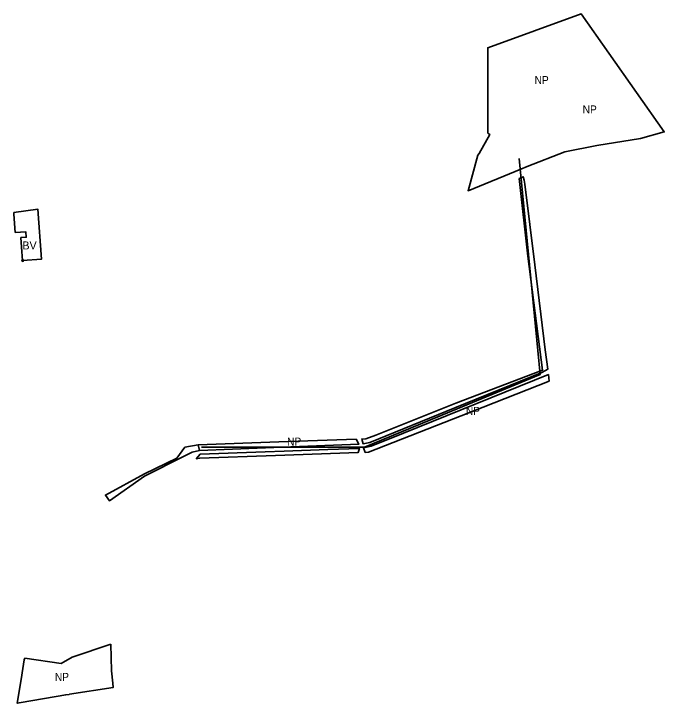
# Model space of a CAD drawing. Extents: x -650276 to -642489, y -1074311 to -1066658.
# Drawn here: x -643464 to -642489, y -1070593 to -1069560 of the extents above; entities that cross this region are included whole.
import ezdxf

# ---------------------------------------------------------------- set-up
doc = ezdxf.new("R2010")
doc.units = 0
doc.header["$LTSCALE"] = 4.8
doc.header["$PDMODE"] = 32
doc.header["$PDSIZE"] = 2.4
for name, color, linetype, lineweight in [('3', 7, 'Continuous', 35), ('48', 7, 'Continuous', 35), ('54', 7, 'Continuous', 35)]:
    doc.layers.add(name, color=color, linetype=linetype, lineweight=lineweight)
doc.layers.add('62', color=7, linetype='Continuous')

msp = doc.modelspace()

# ---------------------------------------------------------------- linework, layer by layer
at = {"layer": '3'}
for points in [[(-643450.3, -1069929.7), (-643422.204, -1069927.68), (-643427.6, -1069852.59), (-643463.51, -1069857.44)], [(-643463.51, -1069857.44), (-643463.31, -1069860.18), (-643461.327, -1069887.84)], [(-643461.327, -1069887.84), (-643445.37, -1069886.7), (-643444.79, -1069894.68), (-643452.77, -1069895.25), (-643451.74, -1069909.63), (-643450.3, -1069929.7)]]:
    msp.add_lwpolyline(points, dxfattribs=at)
msp.add_point((-643450.3, -1069929.7), dxfattribs=at)
at = {"layer": '48'}
for points in [[(-642589.86, -1069757.1), (-642524.14, -1069746.8), (-642488.71, -1069736.85), (-642613.34, -1069559.68), (-642753.18, -1069610.65), (-642753.25, -1069738.59), (-642750.08, -1069740.57), (-642766.27, -1069769), (-642767.89, -1069771.42), (-642782.69, -1069824.93), (-642703.57, -1069792.88), (-642693.99, -1069788.85), (-642637.44, -1069766.81)], [(-642706.3, -1069806.69), (-642693.2, -1069922.89), (-642671.23, -1070094.16), (-642801.19, -1070143.75), (-642921.03, -1070191.32), (-642936.02, -1070197.23), (-642942.12, -1070197.4), (-642940.12, -1070204.42), (-642930.02, -1070202.54), (-642802.38, -1070150.51), (-642671.9, -1070097.32), (-642663.28, -1070092.67), (-642667.19, -1070063.71), (-642682.78, -1069935.98), (-642697.64, -1069815.14), (-642698.77, -1069809.17), (-642700.34, -1069804.12), (-642701.17, -1069804.49)], [(-642936.88, -1070217.27), (-642931.88, -1070217.1), (-642792.87, -1070162.36), (-642661.13, -1070110.48), (-642662.32, -1070100.64), (-642879.2, -1070188.43), (-642928.07, -1070208.21), (-642939.51, -1070210.35)], [(-643066.26, -1070201.69), (-643187.06, -1070205.98), (-643185.16, -1070214.62), (-643086.36, -1070210.57), (-642946.24, -1070204.83), (-642950.42, -1070197.58)], [(-643185.16, -1070214.62), (-643187.06, -1070205.98), (-643207.1, -1070209.72), (-643219.4, -1070225.8), (-643267.55, -1070249.49), (-643326.26, -1070281.43), (-643320, -1070290.2), (-643267.75, -1070252.77), (-643208.09, -1070223.14), (-643196.16, -1070217.22)], [(-643190.42, -1070226.99), (-643184.86, -1070225.91), (-643071.16, -1070221.95), (-642947.42, -1070217.64), (-642945.59, -1070211.49), (-642992.64, -1070213.18), (-643058.07, -1070215.38), (-643086.58, -1070216.57), (-643184.22, -1070220.08)]]:
    msp.add_lwpolyline(points, close=True, dxfattribs=at)
for points in [[(-643452.22, -1070592.35), (-643385.72, -1070580.86), (-643380.35, -1070580.14), (-643380.08, -1070580.09), (-643314.51, -1070569.69), (-643315.27, -1070563.2), (-643317.08, -1070544.75), (-643317.9, -1070504.73)], [(-643317.9, -1070504.73), (-643376.07, -1070524.59), (-643392.41, -1070533.68), (-643446.89, -1070526.01)], [(-643446.89, -1070526.01), (-643447.79, -1070528.63), (-643450.98, -1070547.74), (-643452.14, -1070554.77)], [(-643452.14, -1070554.77), (-643458.42, -1070593.43), (-643452.22, -1070592.35)]]:
    msp.add_lwpolyline(points, dxfattribs=at)
at = {"layer": '54'}
msp.add_lwpolyline([(-643182.326, -1070209.281), (-642937.896, -1070209.281), (-642674.665, -1070100.645), (-642706.002, -1069776.828)], dxfattribs=at)

# ---------------------------------------------------------------- texts
at = {"layer": '62', "width": 0.95}
for p in [(-642682.928, -1069665.096), (-642610.928, -1069709.096), (-642785.928, -1070161.096), (-643053.928, -1070207.096), (-643401.985, -1070559.967)]:
    msp.add_text('NP', height=12, dxfattribs=at).set_placement(p)
at = {"layer": '62'}
msp.add_text('BV', height=12, dxfattribs=at).set_placement((-643450.639, -1069913.037))

doc.saveas('drawing.dxf')
